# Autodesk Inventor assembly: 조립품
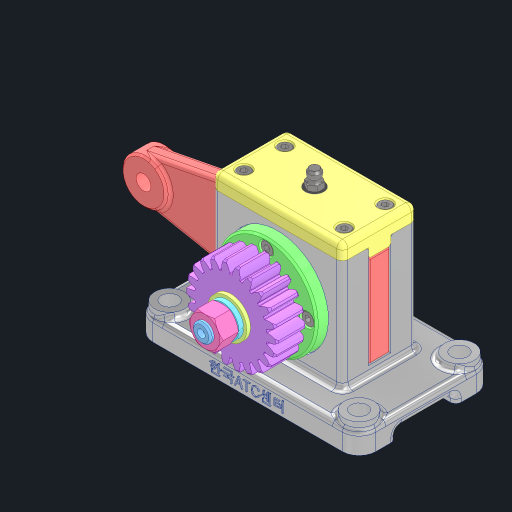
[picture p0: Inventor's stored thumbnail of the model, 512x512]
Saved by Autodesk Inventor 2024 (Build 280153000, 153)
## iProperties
Created: 2025-04
Part Number: 조립품
Document SubType Name: Assembly
Designer: kh_501
Author: kh_501
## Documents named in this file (15)
- C:\Users\kh_501\Desktop\750404V1006\조립품.iam
- C:\Users\kh_501\Desktop\750404V1006\본체.ipt
- C:\Users\kh_501\Desktop\750404V1006\플랜지 오일레스 부시.ipt
- C:\Users\kh_501\Desktop\750404V1006\로드.ipt
- C:\Users\kh_501\Desktop\750404V1006\편심축.ipt
- C:\Users\kh_501\Desktop\750404V1006\앞커버.ipt
- C:\Users\kh_501\Desktop\750404V1006\윗커버.ipt
- C:\Users\kh_501\Desktop\750404V1006\육각 소켓 머리 볼트 M4x10.ipt
- C:\Users\kh_501\Desktop\750404V1006\평행키 4x4x10.ipt
- C:\Users\kh_501\Desktop\750404V1006\스퍼기어.ipt
- C:\Users\kh_501\Desktop\750404V1006\평와셔 M10.ipt
- C:\Users\kh_501\Desktop\750404V1006\스프링와셔 M10.ipt
- C:\Users\kh_501\Desktop\750404V1006\육각 너트 M10.ipt
- C:\Users\kh_501\Desktop\750404V1006\실링.ipt
- C:\Users\kh_501\Desktop\750404V1006\그리스 니플 M6x0.75.ipt
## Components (3 placed, 2 different names)
1. 플랜지 오일레스 부시:1
2. 플랜지 오일레스 부시:2
3. 그리스 니플 M6x0.75:1 — 그리스 니플
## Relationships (1: Angle 1)
- 그리스 니플 [Angle]: 그리스 니플 M6x0.75:1
